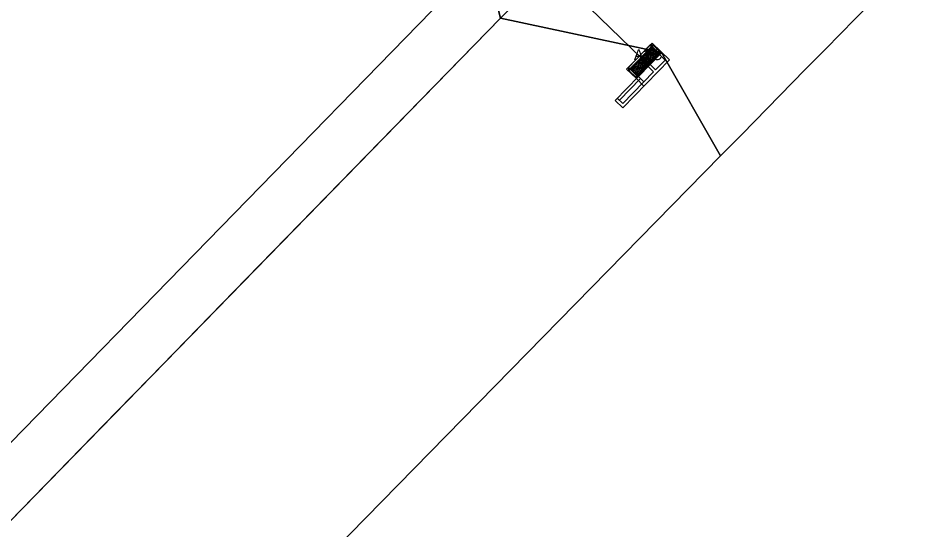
# Model space of a CAD drawing. Extents: x 2252703 to 2264864, y 13787568 to 13790989.
# Drawn here: x 2254795.2 to 2254945.6, y 13790668.5 to 13790752.9 of the extents above; entities that cross this region are included whole.
import ezdxf

# ---------------------------------------------------------------- set-up
doc = ezdxf.new("R2010")
doc.units = 0
for name, color, linetype in [('D_BOXES_1', 7, 'Continuous'), ('D_DRAIN_MISC', 7, 'Continuous'), ('D_DRAIN_NOTES_1', 7, 'Continuous'), ('D_DRN_AREA_X', 7, 'Continuous'), ('D_INLET_1', 7, 'Continuous'), ('D_PIPES_1', 7, 'Continuous')]:
    doc.layers.add(name, color=color, linetype=linetype)

msp = doc.modelspace()

# ---------------------------------------------------------------- linework, layer by layer
at = {"layer": 'D_BOXES_1'}
msp.add_line((2254701.11, 13790587.73), (2254873.56, 13790764.56), dxfattribs=at)
at = {"layer": 'D_DRAIN_MISC'}
for p, q in [((2254900.83, 13790747.05), (2254900.83, 13790747.05)), ((2254898.01, 13790746.3), (2254898.01, 13790746.3)), ((2254899.26, 13790745.08), (2254899.26, 13790745.08)), ((2254897.34, 13790743.47), (2254897.34, 13790743.47)), ((2254900.16, 13790744.21), (2254900.16, 13790744.21))]:
    msp.add_line(p, q, dxfattribs=at)
at = {"layer": 'D_DRN_AREA_X'}
for p, q in [((2254874.76, 13790752.9), (2254868.08, 13790778.99)), ((2254868.08, 13790778.99), (2254874.76, 13790752.9)), ((2254874.76, 13790752.9), (2254892, 13790770.58)), ((2254930.47, 13790749.95), (2254945.76, 13790765.55)), ((2254881.75, 13790760.07), (2254874.76, 13790752.9)), ((2254874.76, 13790752.9), (2254731.66, 13790606.16)), ((2254832.88, 13790709.96), (2254874.76, 13790752.9)), ((2254874.76, 13790752.9), (2254901.34, 13790747.24)), ((2254901.32, 13790747.27), (2254874.76, 13790752.9)), ((2254928.73, 13790748.18), (2254930.47, 13790749.95)), ((2254925.04, 13790744.43), (2254928.73, 13790748.18)), ((2254911.06, 13790730.17), (2254901.32, 13790747.27)), ((2254901.34, 13790747.24), (2254911.06, 13790730.17)), ((2254914.56, 13790733.73), (2254925.04, 13790744.43)), ((2254911.06, 13790730.17), (2254914.56, 13790733.73)), ((2254760.98, 13790577.15), (2254911.06, 13790730.17)), ((2254816.89, 13790693.56), (2254832.88, 13790709.96)), ((2254811.48, 13790688.01), (2254816.89, 13790693.56)), ((2254731.66, 13790606.16), (2254811.48, 13790688.01))]:
    msp.add_line(p, q, dxfattribs=at)
at = {"layer": 'D_INLET_1'}
for p, q in [((2254895.56, 13790744.5), (2254899.75, 13790748.8)), ((2254895.56, 13790744.5), (2254899.75, 13790748.8)), ((2254895.85, 13790744.79), (2254899.46, 13790748.5)), ((2254895.86, 13790744.21), (2254900.05, 13790748.51)), ((2254896.26, 13790744.51), (2254899.75, 13790748.09)), ((2254899.72, 13790748.28), (2254897.92, 13790746.42)), ((2254899.73, 13790748.21), (2254897.98, 13790746.42)), ((2254898, 13790746.42), (2254899.72, 13790748.19)), ((2254898.1, 13790746.57), (2254899.67, 13790748.18)), ((2254899.69, 13790748.25), (2254899.45, 13790748.49)), ((2254899.49, 13790748.52), (2254899.91, 13790748.49)), ((2254899.59, 13790747.91), (2254899.74, 13790748.05)), ((2254899.72, 13790748.28), (2254900.94, 13790747.09)), ((2254899.72, 13790748.19), (2254900.86, 13790747.09)), ((2254899.73, 13790748.21), (2254900.88, 13790747.09)), ((2254899.74, 13790748.05), (2254900.01, 13790747.78)), ((2254899.75, 13790748.8), (2254902.61, 13790746.01)), ((2254899.75, 13790748.09), (2254901.9, 13790746)), ((2254899.76, 13790748.24), (2254899.96, 13790748.45)), ((2254899.81, 13790748.19), (2254900.01, 13790748.4)), ((2254899.94, 13790748.47), (2254901.17, 13790747.27)), ((2254893.68, 13790739.35), (2254901.36, 13790747.23)), ((2254897.92, 13790746.42), (2254899.13, 13790745.24)), ((2254897.98, 13790746.42), (2254899.13, 13790745.3)), ((2254898, 13790746.42), (2254899.13, 13790745.32)), ((2254900.33, 13790744.39), (2254898.13, 13790746.54)), ((2254898.14, 13790746.42), (2254898.28, 13790746.56)), ((2254898.14, 13790746.42), (2254898.41, 13790746.15)), ((2254898.56, 13790746.29), (2254898.28, 13790746.56)), ((2254898.35, 13790746.63), (2254898.49, 13790746.77)), ((2254898.62, 13790746.36), (2254898.35, 13790746.63)), ((2254898.76, 13790746.51), (2254898.49, 13790746.77)), ((2254898.56, 13790746.84), (2254898.7, 13790746.99)), ((2254898.83, 13790746.57), (2254898.56, 13790746.84)), ((2254898.62, 13790746.36), (2254898.76, 13790746.51)), ((2254898.97, 13790746.72), (2254898.7, 13790746.99)), ((2254898.7, 13790746.29), (2254898.84, 13790746.43)), ((2254898.76, 13790747.05), (2254898.9, 13790747.2)), ((2254899.04, 13790746.79), (2254898.76, 13790747.05)), ((2254898.83, 13790746.57), (2254898.97, 13790746.72)), ((2254899.12, 13790746.16), (2254898.84, 13790746.43)), ((2254899.18, 13790746.93), (2254898.9, 13790747.2)), ((2254898.91, 13790746.5), (2254899.05, 13790746.64)), ((2254899.18, 13790746.23), (2254898.91, 13790746.5)), ((2254898.97, 13790747.27), (2254899.11, 13790747.41)), ((2254899.25, 13790747), (2254898.97, 13790747.27)), ((2254899.04, 13790746.79), (2254899.18, 13790746.93)), ((2254899.33, 13790746.37), (2254899.05, 13790746.64)), ((2254899.39, 13790747.14), (2254899.11, 13790747.41)), ((2254899.11, 13790746.71), (2254899.26, 13790746.86)), ((2254899.39, 13790746.44), (2254899.11, 13790746.71)), ((2254900.88, 13790747.09), (2254899.13, 13790745.3)), ((2254900.94, 13790747.09), (2254899.13, 13790745.24)), ((2254900.86, 13790747.09), (2254899.13, 13790745.32)), ((2254899.18, 13790747.48), (2254899.32, 13790747.63)), ((2254899.45, 13790747.21), (2254899.18, 13790747.48)), ((2254899.25, 13790747), (2254899.39, 13790747.14)), ((2254899.53, 13790746.59), (2254899.26, 13790746.86)), ((2254899.59, 13790747.36), (2254899.32, 13790747.63)), ((2254899.32, 13790746.92), (2254899.46, 13790747.07)), ((2254899.6, 13790746.65), (2254899.32, 13790746.92)), ((2254899.39, 13790747.69), (2254899.53, 13790747.84)), ((2254899.66, 13790747.42), (2254899.39, 13790747.69)), ((2254899.39, 13790746.44), (2254899.53, 13790746.59)), ((2254899.45, 13790747.21), (2254899.59, 13790747.36)), ((2254899.74, 13790746.8), (2254899.46, 13790747.07)), ((2254899.47, 13790746.37), (2254899.61, 13790746.51)), ((2254899.8, 13790747.57), (2254899.53, 13790747.84)), ((2254899.53, 13790747.14), (2254899.67, 13790747.28)), ((2254899.81, 13790746.87), (2254899.53, 13790747.14)), ((2254899.87, 13790747.64), (2254899.59, 13790747.91)), ((2254899.6, 13790746.65), (2254899.74, 13790746.8)), ((2254899.88, 13790746.24), (2254899.61, 13790746.51)), ((2254899.66, 13790747.42), (2254899.8, 13790747.57)), ((2254899.95, 13790747.01), (2254899.67, 13790747.28)), ((2254899.68, 13790746.58), (2254899.82, 13790746.73)), ((2254899.95, 13790746.31), (2254899.68, 13790746.58)), ((2254899.74, 13790747.35), (2254899.88, 13790747.5)), ((2254900.01, 13790747.08), (2254899.74, 13790747.35)), ((2254899.81, 13790746.87), (2254899.95, 13790747.01)), ((2254900.09, 13790746.46), (2254899.82, 13790746.73)), ((2254899.87, 13790747.64), (2254900.01, 13790747.78)), ((2254900.16, 13790747.23), (2254899.88, 13790747.5)), ((2254899.88, 13790746.79), (2254900.02, 13790746.94)), ((2254900.16, 13790746.52), (2254899.88, 13790746.79)), ((2254899.94, 13790747.56), (2254900.09, 13790747.71)), ((2254900.22, 13790747.29), (2254899.94, 13790747.56)), ((2254900.09, 13790746.46), (2254899.95, 13790746.31)), ((2254900.01, 13790747.08), (2254900.16, 13790747.23)), ((2254900.3, 13790746.67), (2254900.02, 13790746.94)), ((2254900.09, 13790747.71), (2254900.36, 13790747.44)), ((2254900.09, 13790747.01), (2254900.23, 13790747.15)), ((2254900.36, 13790746.74), (2254900.09, 13790747.01)), ((2254900.3, 13790746.67), (2254900.16, 13790746.52)), ((2254900.21, 13790746.29), (2254901.17, 13790747.27)), ((2254900.22, 13790747.29), (2254900.36, 13790747.44)), ((2254900.51, 13790746.88), (2254900.23, 13790747.15)), ((2254900.3, 13790747.22), (2254900.44, 13790747.36)), ((2254900.57, 13790746.95), (2254900.3, 13790747.22)), ((2254900.51, 13790746.88), (2254900.36, 13790746.74)), ((2254900.44, 13790747.36), (2254900.71, 13790747.1)), ((2254900.71, 13790747.1), (2254900.57, 13790746.95)), ((2254900.85, 13790747.17), (2254901.06, 13790747.38)), ((2254900.91, 13790747.12), (2254901.11, 13790747.33)), ((2254894.93, 13790738.13), (2254902.61, 13790746.01)), ((2254896.08, 13790744.54), (2254897.89, 13790746.39)), ((2254896.14, 13790744.54), (2254897.89, 13790746.33)), ((2254897.89, 13790746.31), (2254896.16, 13790744.54)), ((2254896.17, 13790744.59), (2254897.75, 13790746.21)), ((2254896.86, 13790745.1), (2254896.72, 13790744.96)), ((2254896.99, 13790744.69), (2254896.72, 13790744.96)), ((2254897.14, 13790744.84), (2254896.86, 13790745.1)), ((2254897.07, 13790745.32), (2254896.93, 13790745.17)), ((2254897.2, 13790744.9), (2254896.93, 13790745.17)), ((2254897.34, 13790745.05), (2254897.07, 13790745.32)), ((2254897.12, 13790743.12), (2254900.21, 13790746.29)), ((2254897.28, 13790745.53), (2254897.13, 13790745.38)), ((2254897.41, 13790745.12), (2254897.13, 13790745.38)), ((2254897.34, 13790745.05), (2254897.2, 13790744.9)), ((2254897.55, 13790745.26), (2254897.28, 13790745.53)), ((2254897.42, 13790744.98), (2254897.28, 13790744.83)), ((2254897.29, 13790743.42), (2254899.04, 13790745.21)), ((2254897.29, 13790743.44), (2254899.02, 13790745.21)), ((2254897.3, 13790743.35), (2254899.1, 13790745.21)), ((2254897.48, 13790745.74), (2254897.34, 13790745.6)), ((2254897.62, 13790745.33), (2254897.34, 13790745.6)), ((2254897.55, 13790745.26), (2254897.41, 13790745.12)), ((2254897.7, 13790744.71), (2254897.42, 13790744.98)), ((2254897.76, 13790745.48), (2254897.48, 13790745.74)), ((2254897.63, 13790745.19), (2254897.49, 13790745.04)), ((2254897.76, 13790744.77), (2254897.49, 13790745.04)), ((2254897.69, 13790745.96), (2254897.55, 13790745.81)), ((2254897.82, 13790745.54), (2254897.55, 13790745.81)), ((2254897.76, 13790745.48), (2254897.62, 13790745.33)), ((2254897.9, 13790744.92), (2254897.63, 13790745.19)), ((2254897.97, 13790745.69), (2254897.69, 13790745.96)), ((2254897.84, 13790745.4), (2254897.69, 13790745.26)), ((2254897.97, 13790744.99), (2254897.69, 13790745.26)), ((2254897.9, 13790746.17), (2254897.76, 13790746.02)), ((2254898.03, 13790745.76), (2254897.76, 13790746.02)), ((2254897.9, 13790744.92), (2254897.76, 13790744.77)), ((2254899.98, 13790744.03), (2254897.78, 13790746.18)), ((2254897.97, 13790745.69), (2254897.82, 13790745.54)), ((2254898.11, 13790745.13), (2254897.84, 13790745.4)), ((2254897.89, 13790746.39), (2254899.1, 13790745.21)), ((2254897.89, 13790746.33), (2254899.04, 13790745.21)), ((2254897.89, 13790746.31), (2254899.02, 13790745.21)), ((2254897.9, 13790746.17), (2254898.17, 13790745.9)), ((2254898.04, 13790745.61), (2254897.9, 13790745.47)), ((2254898.18, 13790745.2), (2254897.9, 13790745.47)), ((2254898.11, 13790745.13), (2254897.97, 13790744.99)), ((2254898.17, 13790745.9), (2254898.03, 13790745.76)), ((2254898.32, 13790745.34), (2254898.04, 13790745.61)), ((2254898.19, 13790745.06), (2254898.05, 13790744.91)), ((2254898.32, 13790744.64), (2254898.05, 13790744.91)), ((2254898.25, 13790745.83), (2254898.11, 13790745.68)), ((2254898.39, 13790745.41), (2254898.11, 13790745.68)), ((2254898.32, 13790745.34), (2254898.18, 13790745.2)), ((2254898.46, 13790744.79), (2254898.19, 13790745.06)), ((2254898.25, 13790745.83), (2254898.53, 13790745.56)), ((2254898.4, 13790745.27), (2254898.25, 13790745.12)), ((2254898.53, 13790744.86), (2254898.25, 13790745.12)), ((2254898.53, 13790745.56), (2254898.39, 13790745.41)), ((2254898.67, 13790745), (2254898.4, 13790745.27)), ((2254898.41, 13790746.15), (2254898.56, 13790746.29)), ((2254898.6, 13790745.48), (2254898.46, 13790745.34)), ((2254898.74, 13790745.07), (2254898.46, 13790745.34)), ((2254898.49, 13790746.07), (2254898.63, 13790746.22)), ((2254898.49, 13790746.07), (2254898.77, 13790745.8)), ((2254898.53, 13790744.86), (2254898.67, 13790745)), ((2254898.6, 13790745.48), (2254898.88, 13790745.21)), ((2254898.91, 13790745.95), (2254898.63, 13790746.22)), ((2254898.98, 13790746.02), (2254898.7, 13790746.29)), ((2254898.74, 13790745.07), (2254898.88, 13790745.21)), ((2254898.77, 13790745.8), (2254898.91, 13790745.95)), ((2254898.84, 13790745.73), (2254898.99, 13790745.87)), ((2254898.84, 13790745.73), (2254899.12, 13790745.46)), ((2254898.98, 13790746.02), (2254899.12, 13790746.16)), ((2254899.26, 13790745.61), (2254898.99, 13790745.87)), ((2254899.05, 13790745.94), (2254899.19, 13790746.09)), ((2254899.33, 13790745.67), (2254899.05, 13790745.94)), ((2254899.26, 13790745.61), (2254899.12, 13790745.46)), ((2254899.18, 13790746.23), (2254899.33, 13790746.37)), ((2254899.47, 13790745.82), (2254899.19, 13790746.09)), ((2254899.26, 13790746.15), (2254899.4, 13790746.3)), ((2254899.53, 13790745.89), (2254899.26, 13790746.15)), ((2254899.47, 13790745.82), (2254899.33, 13790745.67)), ((2254899.68, 13790746.03), (2254899.4, 13790746.3)), ((2254899.74, 13790746.1), (2254899.47, 13790746.37)), ((2254899.68, 13790746.03), (2254899.53, 13790745.89)), ((2254899.88, 13790746.24), (2254899.74, 13790746.1)), ((2254900.33, 13790744.39), (2254901.9, 13790746)), ((2254894.92, 13790738.84), (2254899.98, 13790744.03)), ((2254895.56, 13790744.5), (2254897.17, 13790742.93)), ((2254895.83, 13790744.76), (2254895.87, 13790744.35)), ((2254896.11, 13790744.57), (2254895.86, 13790744.81)), ((2254895.89, 13790744.32), (2254897.12, 13790743.12)), ((2254896.11, 13790744.51), (2254895.91, 13790744.3)), ((2254896.16, 13790744.46), (2254895.96, 13790744.25)), ((2254896.08, 13790744.54), (2254897.3, 13790743.35)), ((2254896.14, 13790744.54), (2254897.29, 13790743.42)), ((2254896.16, 13790744.54), (2254897.29, 13790743.44)), ((2254896.26, 13790744.51), (2254898.41, 13790742.42)), ((2254896.45, 13790744.68), (2254896.3, 13790744.53)), ((2254896.3, 13790744.53), (2254896.58, 13790744.27)), ((2254896.72, 13790744.41), (2254896.45, 13790744.68)), ((2254896.65, 13790744.89), (2254896.51, 13790744.75)), ((2254896.79, 13790744.48), (2254896.51, 13790744.75)), ((2254896.72, 13790744.41), (2254896.58, 13790744.27)), ((2254896.93, 13790744.62), (2254896.65, 13790744.89)), ((2254896.8, 13790744.34), (2254896.66, 13790744.19)), ((2254896.66, 13790744.19), (2254896.93, 13790743.92)), ((2254896.93, 13790744.62), (2254896.79, 13790744.48)), ((2254897.07, 13790744.07), (2254896.8, 13790744.34)), ((2254897.01, 13790744.55), (2254896.86, 13790744.4)), ((2254897.14, 13790744.13), (2254896.86, 13790744.4)), ((2254897.07, 13790744.07), (2254896.93, 13790743.92)), ((2254897.14, 13790744.84), (2254896.99, 13790744.69)), ((2254897.28, 13790744.28), (2254897.01, 13790744.55)), ((2254897.15, 13790743.99), (2254897.01, 13790743.85)), ((2254897.01, 13790743.85), (2254897.28, 13790743.58)), ((2254897.21, 13790743.44), (2254897.01, 13790743.23)), ((2254897.21, 13790744.76), (2254897.07, 13790744.62)), ((2254897.35, 13790744.35), (2254897.07, 13790744.62)), ((2254897.28, 13790744.28), (2254897.14, 13790744.13)), ((2254897.43, 13790743.72), (2254897.15, 13790743.99)), ((2254897.49, 13790744.49), (2254897.21, 13790744.76)), ((2254897.36, 13790744.2), (2254897.22, 13790744.06)), ((2254897.49, 13790743.79), (2254897.22, 13790744.06)), ((2254897.56, 13790744.56), (2254897.28, 13790744.83)), ((2254897.28, 13790743.58), (2254897.43, 13790743.72)), ((2254897.49, 13790744.49), (2254897.35, 13790744.35)), ((2254897.63, 13790743.94), (2254897.36, 13790744.2)), ((2254897.57, 13790744.42), (2254897.42, 13790744.27)), ((2254897.7, 13790744), (2254897.42, 13790744.27)), ((2254897.49, 13790743.79), (2254897.63, 13790743.94)), ((2254897.7, 13790744.71), (2254897.56, 13790744.56)), ((2254897.84, 13790744.15), (2254897.57, 13790744.42)), ((2254897.77, 13790744.63), (2254897.63, 13790744.48)), ((2254897.91, 13790744.22), (2254897.63, 13790744.48)), ((2254897.7, 13790744), (2254897.84, 13790744.15)), ((2254898.05, 13790744.36), (2254897.77, 13790744.63)), ((2254897.98, 13790744.84), (2254897.84, 13790744.7)), ((2254898.11, 13790744.43), (2254897.84, 13790744.7)), ((2254897.91, 13790744.22), (2254898.05, 13790744.36)), ((2254898.26, 13790744.58), (2254897.98, 13790744.84)), ((2254898.11, 13790744.43), (2254898.26, 13790744.58)), ((2254898.32, 13790744.64), (2254898.46, 13790744.79)), ((2254894.38, 13790739.36), (2254897.87, 13790742.94)), ((2254897.26, 13790743.39), (2254897.06, 13790743.18)), ((2254897.17, 13790742.93), (2254898.42, 13790741.71)), ((2254894.93, 13790738.13), (2254893.68, 13790739.35)), ((2254894.92, 13790738.84), (2254894.03, 13790739.71))]:
    msp.add_line(p, q, dxfattribs=at)
for centre, start_param, end_param in [((2254899.5, 13790748.47), 5.480245, 6.283185), ((2254899.91, 13790748.44), 4.712389, 5.480245), ((2254895.88, 13790744.76), 0, 0.80294), ((2254895.92, 13790744.35), 0.80294, 1.570796)]:
    msp.add_ellipse(centre, major_axis=(-0.0341, 0.0332), ratio=0.877193, start_param=start_param, end_param=end_param, dxfattribs=at)
at = {"layer": 'D_PIPES_1'}
msp.add_line((2254898.01, 13790746.3), (2254879.22, 13790764.63), dxfattribs=at)

# ---------------------------------------------------------------- texts
at = {"layer": 'D_DRAIN_NOTES_1'}
msp.add_text('A2C', height=1.8, dxfattribs=at).set_placement((2254896.75, 13790745.98))

doc.saveas('drawing.dxf')
